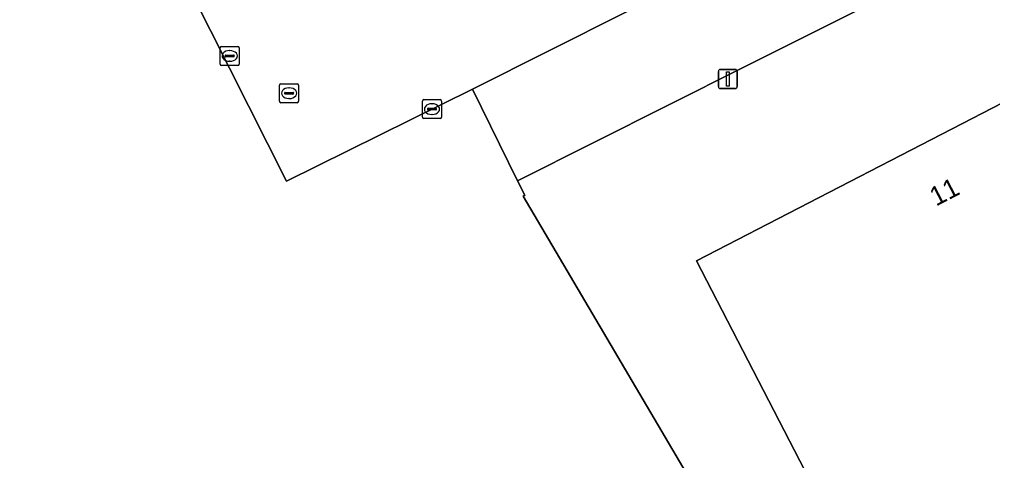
# Model space of a CAD drawing. Extents: x 158455 to 159797, y 387218 to 388672.
# Drawn here: x 158935 to 158986.1, y 387656.2 to 387679.3 of the extents above; entities that cross this region are included whole.
import ezdxf

# ---------------------------------------------------------------- set-up
doc = ezdxf.new("R2010")
doc.units = 0
for name, color, linetype in [('IMGEO_Erf', 7, 'Continuous'), ('IMGEO_Groenvoorziening', 7, 'Continuous'), ('IMGEO_Kolk', 7, 'Continuous'), ('IMGEO_Lichtmast', 7, 'Continuous'), ('IMGEO_Pand', 7, 'Continuous'), ('IMGEO_Pand_nummerreeks', 7, 'Continuous'), ('IMGEO_Parkeervlak_open', 7, 'Continuous'), ('IMGEO_Rijbaan_lokaal_open', 7, 'Continuous'), ('IMGEO_Rioolput', 7, 'Continuous')]:
    doc.layers.add(name, color=color, linetype=linetype)

msp = doc.modelspace()

# ---------------------------------------------------------------- linework, layer by layer
at = {"layer": 'IMGEO_Erf'}
msp.add_lwpolyline([(158994.143, 387678.837), (158992.623, 387684.195), (158992.064, 387683.946), (158991.361, 387685.5), (158990.588, 387685.178), (158990.433, 387685.56), (158973.044, 387676.827), (158961.124, 387670.85), (158961.498, 387670.092), (158961.411, 387670.041), (158973.845, 387648.946), (158978.384, 387651.425), (158970.526, 387666.636)], close=True, dxfattribs=at)
at = {"layer": 'IMGEO_Groenvoorziening'}
for points in [[(158961.411, 387670.041), (158961.498, 387670.092), (158961.124, 387670.85), (158958.754, 387675.659), (158948.984, 387670.834), (158932.006, 387704.453), (158930.794, 387703.7), (158910.128, 387690.749)], [(159012.547, 387660.697), (159009.869, 387665.772), (159005.303, 387663.428), (159005, 387663.27), (159000.944, 387660.986), (159000.123, 387662.655), (158978.384, 387651.425), (158973.845, 387648.946), (158961.411, 387670.041)]]:
    msp.add_lwpolyline(points, dxfattribs=at)
at = {"layer": 'IMGEO_Kolk'}
for p, q in [((158945.499, 387676.979), (158945.499, 387677.831)), ((158945.574, 387677.905), (158946.426, 387677.905)), ((158945.758, 387677.399), (158945.758, 387677.411)), ((158945.801, 387677.448), (158946.199, 387677.448)), ((158945.987, 387677.685), (158946.012, 387677.685)), ((158946.242, 387677.411), (158946.242, 387677.399)), ((158946.5, 387677.831), (158946.5, 387676.979)), ((158946.426, 387676.905), (158945.574, 387676.905)), ((158946.196, 387677.362), (158945.798, 387677.362)), ((158946.01, 387677.125), (158945.985, 387677.125)), ((158956.126, 387674.185), (158956.126, 387675.037)), ((158956.201, 387675.111), (158957.053, 387675.111)), ((158956.614, 387674.891), (158956.639, 387674.891)), ((158957.127, 387675.037), (158957.127, 387674.185)), ((158956.385, 387674.605), (158956.385, 387674.617)), ((158956.823, 387674.568), (158956.425, 387674.568)), ((158956.428, 387674.654), (158956.826, 387674.654)), ((158956.637, 387674.331), (158956.612, 387674.331)), ((158956.869, 387674.617), (158956.869, 387674.605)), ((158957.053, 387674.111), (158956.201, 387674.111))]:
    msp.add_line(p, q, dxfattribs=at)
for points in [[(158945.499, 387676.979), (158945.499, 387677.831)], [(158945.574, 387677.905), (158946.426, 387677.905)], [(158946.5, 387677.831), (158946.5, 387676.979)], [(158946.426, 387676.905), (158945.574, 387676.905)], [(158956.126, 387674.185), (158956.126, 387675.037)], [(158956.201, 387675.111), (158957.053, 387675.111)], [(158957.127, 387675.037), (158957.127, 387674.185)], [(158957.053, 387674.111), (158956.201, 387674.111)]]:
    msp.add_lwpolyline(points, dxfattribs=at)
for centre, radius, start, end in [((158945.576, 387677.829), 0.0765, 91.552, 178.448), ((158945.576, 387677.829), 0.0765, 91.552, 178.448), ((158945.798, 387677.408), 0.0403, 85.8775, 175.7526), ((158945.795, 387677.398), 0.0366, 178.938, 274.7102), ((158946.199, 387677.405), 0.043, 264.8664, 352.4533), ((158946.203, 387677.41), 0.0386, 1.7309, 96.639), ((158946.424, 387677.829), 0.0765, 1.552, 88.448), ((158946.424, 387677.829), 0.0765, 1.552, 88.448), ((158945.576, 387676.981), 0.0765, 181.552, 268.448), ((158945.576, 387676.981), 0.0765, 181.552, 268.448), ((158946.424, 387676.981), 0.0765, 271.552, 358.448), ((158946.424, 387676.981), 0.0765, 271.552, 358.448), ((158956.203, 387675.035), 0.0765, 91.552, 178.448), ((158956.203, 387675.035), 0.0765, 91.552, 178.448), ((158957.051, 387675.035), 0.0765, 1.552, 88.448), ((158957.051, 387675.035), 0.0765, 1.552, 88.448), ((158956.425, 387674.614), 0.0403, 85.8775, 175.7526), ((158956.422, 387674.604), 0.0366, 178.938, 274.7102), ((158956.826, 387674.611), 0.043, 264.8664, 352.4533), ((158956.83, 387674.616), 0.0386, 1.7309, 96.639), ((158956.203, 387674.187), 0.0765, 181.552, 268.448), ((158956.203, 387674.187), 0.0765, 181.552, 268.448), ((158957.051, 387674.187), 0.0765, 271.552, 358.448), ((158957.051, 387674.187), 0.0765, 271.552, 358.448)]:
    msp.add_arc(centre, radius, start, end, dxfattribs=at)
for centre, major_axis, ratio, start_param, end_param in [((158945.986, 387677.405), (-0.387, 0.002), 0.722429, 4.712389, 7.853982), ((158946.011, 387677.405), (-0.39, 0.002), 0.717154, 1.570796, 4.712389), ((158956.613, 387674.611), (-0.387, 0.002), 0.722429, 4.712389, 7.853982), ((158956.638, 387674.611), (-0.39, 0.002), 0.717154, 1.570796, 4.712389)]:
    msp.add_ellipse(centre, major_axis=major_axis, ratio=ratio, start_param=start_param, end_param=end_param, dxfattribs=at)
at = {"layer": 'IMGEO_Lichtmast'}
for p, q in [((158971.675, 387675.794), (158971.675, 387676.594)), ((158971.675, 387676.594), (158971.675, 387675.794)), ((158971.775, 387676.694), (158972.565, 387676.694)), ((158972.565, 387676.694), (158971.775, 387676.694)), ((158972.665, 387676.594), (158972.665, 387675.794)), ((158972.665, 387675.794), (158972.665, 387676.594)), ((158972.565, 387675.694), (158971.775, 387675.694)), ((158971.775, 387675.694), (158972.565, 387675.694))]:
    msp.add_line(p, q, dxfattribs=at)
msp.add_lwpolyline([(158972.095, 387676.569), (158972.245, 387676.569), (158972.245, 387675.819), (158972.095, 387675.819), (158972.095, 387676.569)], dxfattribs=at)
for centre, start, end in [((158971.775, 387676.594), 90, 180), ((158971.775, 387676.594), 90, 180), ((158972.565, 387676.594), 0, 90), ((158972.565, 387676.594), 360, 90), ((158971.775, 387675.794), 180, 270), ((158971.775, 387675.794), 180, 270), ((158972.565, 387675.794), 270, 0), ((158972.565, 387675.794), 270, 0)]:
    msp.add_arc(centre, 0.1, start, end, dxfattribs=at)
at = {"layer": 'IMGEO_Pand'}
msp.add_lwpolyline([(158998.739, 387669.992), (158997.047, 387669.17), (158994.143, 387678.837), (158970.526, 387666.636), (158978.384, 387651.425), (159000.123, 387662.655), (159002.043, 387663.647)], close=True, dxfattribs=at)
at = {"layer": 'IMGEO_Parkeervlak_open'}
msp.add_lwpolyline([(158988.077, 387690.38), (158970.817, 387681.727), (158958.754, 387675.659), (158961.124, 387670.85), (158973.044, 387676.827), (158990.433, 387685.56)], close=True, dxfattribs=at)
at = {"layer": 'IMGEO_Rijbaan_lokaal_open'}
msp.add_lwpolyline([(158950.005, 387681.439), (158940.681, 387700.044), (158937.272, 387706.788), (158936.928, 387707.508), (158932.006, 387704.453), (158948.984, 387670.834), (158958.754, 387675.659), (158970.817, 387681.727), (158988.077, 387690.38), (158992.643, 387692.668)], dxfattribs=at)
at = {"layer": 'IMGEO_Rioolput'}
for p, q in [((158948.619, 387675.022), (158948.619, 387675.874)), ((158948.694, 387675.948), (158949.546, 387675.948)), ((158949.62, 387675.874), (158949.62, 387675.022)), ((158948.878, 387675.442), (158948.878, 387675.454)), ((158949.316, 387675.405), (158948.918, 387675.405)), ((158948.921, 387675.491), (158949.319, 387675.491)), ((158949.107, 387675.728), (158949.132, 387675.728)), ((158949.362, 387675.454), (158949.362, 387675.442)), ((158949.546, 387674.948), (158948.694, 387674.948)), ((158949.13, 387675.168), (158949.105, 387675.168))]:
    msp.add_line(p, q, dxfattribs=at)
for points in [[(158948.619, 387675.022), (158948.619, 387675.874)], [(158948.694, 387675.948), (158949.546, 387675.948)], [(158949.62, 387675.874), (158949.62, 387675.022)], [(158949.546, 387674.948), (158948.694, 387674.948)]]:
    msp.add_lwpolyline(points, dxfattribs=at)
for centre, radius, start, end in [((158948.696, 387675.872), 0.0765, 91.552, 178.448), ((158948.696, 387675.872), 0.0765, 91.552, 178.448), ((158949.544, 387675.872), 0.0765, 1.552, 88.448), ((158949.544, 387675.872), 0.0765, 1.552, 88.448), ((158948.918, 387675.451), 0.0403, 85.8775, 175.7526), ((158948.915, 387675.441), 0.0366, 178.938, 274.7102), ((158949.319, 387675.448), 0.043, 264.8664, 352.4533), ((158949.323, 387675.453), 0.0386, 1.7309, 96.639), ((158948.696, 387675.024), 0.0765, 181.552, 268.448), ((158948.696, 387675.024), 0.0765, 181.552, 268.448), ((158949.544, 387675.024), 0.0765, 271.552, 358.448), ((158949.544, 387675.024), 0.0765, 271.552, 358.448)]:
    msp.add_arc(centre, radius, start, end, dxfattribs=at)
for centre, major_axis, ratio, start_param, end_param in [((158949.106, 387675.448), (-0.387, 0.002), 0.722429, 4.712389, 7.853982), ((158949.131, 387675.448), (-0.39, 0.002), 0.717154, 1.570796, 4.712389)]:
    msp.add_ellipse(centre, major_axis=major_axis, ratio=ratio, start_param=start_param, end_param=end_param, dxfattribs=at)

# ---------------------------------------------------------------- texts
at = {"layer": 'IMGEO_Pand_nummerreeks'}
msp.add_text('11', height=1, rotation=27.1473, dxfattribs=at).set_placement((158983.11, 387669.49))

doc.saveas('drawing.dxf')
